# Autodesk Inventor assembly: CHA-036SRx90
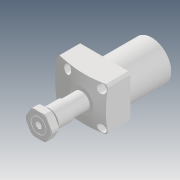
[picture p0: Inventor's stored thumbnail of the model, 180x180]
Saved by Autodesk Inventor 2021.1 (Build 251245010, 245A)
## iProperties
Created: 2019-12
Part Number: CHA-036SRx90
Description: STEP AP203
Document SubType Name: Assembly
Designer: user
Title: CHA-036SRx90.STEP
Revision Number: ÈÎºÎ
Sending System: SolidWorks 2017
Preprocessor: SwSTEP 2.0
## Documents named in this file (5)
- D:\Vault_2016\Projekty\Clamptek\Hydraulic\CHA\CHA\CHA-036\Inventor\CHA-036SRx90\CHA-036SRx90.iam
- D:\Vault_2016\Projekty\Clamptek\Hydraulic\CHA\CHA\CHA-036\Inventor\CHA-036SRx90\CHA-036±¾Ìå_1.ipt
- D:\Vault_2016\Projekty\Clamptek\Hydraulic\CHA\CHA\CHA-036\Inventor\CHA-036SRx90\CHA-036»îÈû¸Ë_1.ipt
- D:\Vault_2016\Projekty\Clamptek\Hydraulic\CHA\CHA\CHA-036\Inventor\CHA-036SRx90\CHA-036S×¶Ì×.ipt
- D:\Vault_2016\Projekty\Clamptek\Hydraulic\CHA\CHA\CHA-036\Inventor\CHA-036SRx90\CHA-036ÂÝÄ¸.ipt
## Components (4 placed, 4 different names)
1. CHA-036±¾Ìå_1_1
2. CHA-036»îÈû¸Ë_1_2
3. CHA-036S×¶Ì×_3
4. CHA-036ÂÝÄ¸_4
